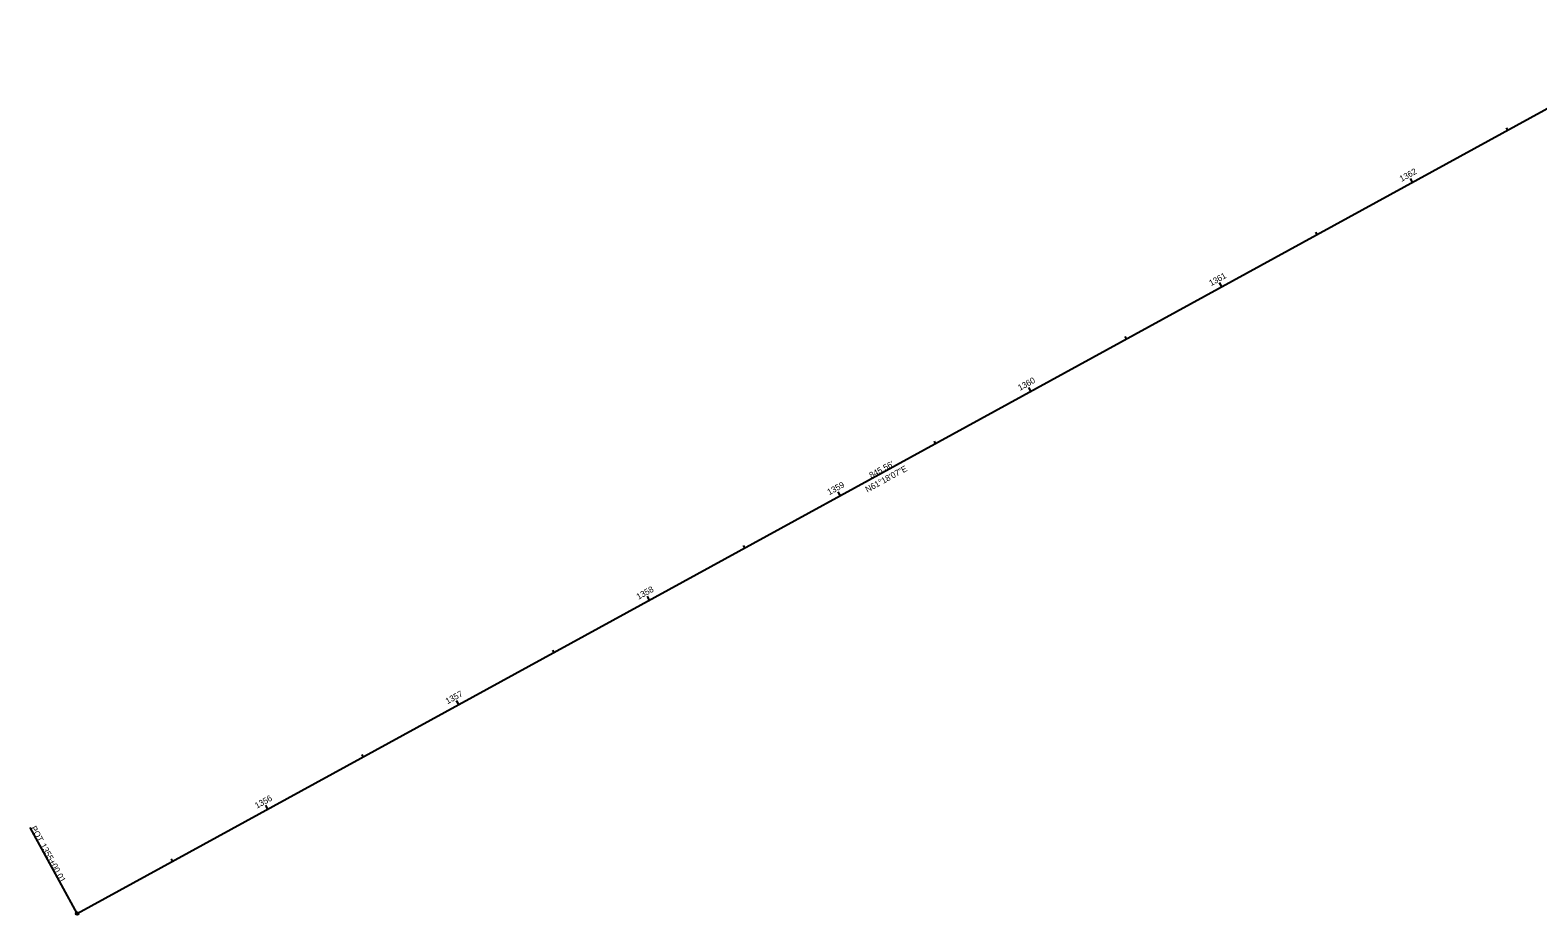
# Model space of a CAD drawing. Extents: x 153500 to 156291, y 370917 to 372075.
# Drawn here: x 153500 to 154193, y 370917 to 371324 of the extents above; entities that cross this region are included whole.
import ezdxf

# ---------------------------------------------------------------- set-up
doc = ezdxf.new("R2010")
doc.units = 0
for name, color, linetype in [('Default', 7, 'Continuous'), ('GE_X_Alignment', 7, 'Continuous'), ('GE_X_Alignment_1000_Stations', 7, 'Continuous'), ('GE_X_Alignment_100_Stations', 7, 'Continuous'), ('GE_X_Alignment_500_Stations', 7, 'Continuous')]:
    doc.layers.add(name, color=color, linetype=linetype)

msp = doc.modelspace()

# ---------------------------------------------------------------- linework, layer by layer
at = {"layer": 'Default'}
msp.add_line((153521.23, 370917.9), (154262.92, 371323.93), dxfattribs=at)
at = {"layer": 'GE_X_Alignment'}
msp.add_line((153521.23, 370917.9), (154262.92, 371323.93), dxfattribs=at)
at = {"layer": 'GE_X_Alignment_1000_Stations'}
for p, q in [((153959.8, 371157.99), (153958.84, 371159.74)), ((153521.23, 370917.9), (153499.62, 370957.37))]:
    msp.add_line(p, q, dxfattribs=at)
msp.add_circle((153521.23, 370917.9), 0.6, dxfattribs=at)
at = {"layer": 'GE_X_Alignment_100_Stations'}
for p, q in [((154179.09, 371278.04), (154178.51, 371279.09)), ((154135.23, 371254.03), (154134.27, 371255.78)), ((154091.37, 371230.02), (154090.8, 371231.07)), ((154047.52, 371206.01), (154046.55, 371207.76)), ((154003.66, 371182), (154003.08, 371183.05)), ((153959.8, 371157.99), (153958.84, 371159.74)), ((153915.94, 371133.98), (153915.36, 371135.03)), ((153872.08, 371109.97), (153871.12, 371111.72)), ((153828.22, 371085.96), (153827.65, 371087.01)), ((153784.37, 371061.95), (153783.41, 371063.7)), ((153740.51, 371037.94), (153739.93, 371038.99)), ((153696.65, 371013.93), (153695.69, 371015.69)), ((153652.79, 370989.92), (153652.22, 370990.97)), ((153608.93, 370965.91), (153607.97, 370967.67)), ((153521.23, 370917.9), (153499.62, 370957.37)), ((153565.08, 370941.9), (153564.5, 370942.95))]:
    msp.add_line(p, q, dxfattribs=at)
msp.add_circle((153521.23, 370917.9), 0.6, dxfattribs=at)
at = {"layer": 'GE_X_Alignment_500_Stations'}
for p, q in [((154135.23, 371254.03), (154134.66, 371255.08)), ((154047.52, 371206.01), (154046.94, 371207.06)), ((153959.8, 371157.99), (153958.84, 371159.74)), ((153872.08, 371109.97), (153871.51, 371111.02)), ((153784.37, 371061.95), (153783.79, 371063)), ((153696.65, 371013.93), (153696.07, 371014.98)), ((153608.93, 370965.91), (153608.36, 370966.96)), ((153521.23, 370917.9), (153499.62, 370957.37))]:
    msp.add_line(p, q, dxfattribs=at)
msp.add_circle((153521.23, 370917.9), 0.6, dxfattribs=at)

# ---------------------------------------------------------------- texts
at = {"layer": 'GE_X_Alignment_1000_Stations'}
for s, rotation, p in [('1360', 28.69803, (153954.74, 371158.13)), ('N61°18\'07"E', 28.69803, (153884.57, 371111.33)), ("845.56'", 28.69803, (153886.36, 371117.84)), ('POT', 298.69803, (153499.76, 370957.21)), ('1355+00.01', 298.69803, (153504.14, 370949.21))]:
    msp.add_text(s, height=2.8, rotation=rotation, dxfattribs=at).set_placement(p)
at = {"layer": 'GE_X_Alignment_100_Stations'}
for s, rotation, p in [('1362', 28.69803, (154130.18, 371254.17)), ('1361', 28.69803, (154042.61, 371206.23)), ('1360', 28.69803, (153954.74, 371158.13)), ('N61°18\'07"E', 28.69803, (153884.57, 371111.33)), ("845.56'", 28.69803, (153886.36, 371117.84)), ('1359', 28.69803, (153867.05, 371110.12)), ('1358', 28.69803, (153779.31, 371062.09)), ('1357', 28.69803, (153691.54, 371014.04)), ('1356', 28.69803, (153603.88, 370966.05)), ('POT', 298.69803, (153499.76, 370957.21)), ('1355+00.01', 298.69803, (153504.14, 370949.21))]:
    msp.add_text(s, height=2.8, rotation=rotation, dxfattribs=at).set_placement(p)
at = {"layer": 'GE_X_Alignment_500_Stations'}
for s, rotation, p in [('1360', 28.69803, (153954.74, 371158.13)), ('N61°18\'07"E', 28.69803, (153884.57, 371111.33)), ("845.56'", 28.69803, (153886.36, 371117.84)), ('POT', 298.69803, (153499.76, 370957.21)), ('1355+00.01', 298.69803, (153504.14, 370949.21))]:
    msp.add_text(s, height=2.8, rotation=rotation, dxfattribs=at).set_placement(p)

doc.saveas('drawing.dxf')
